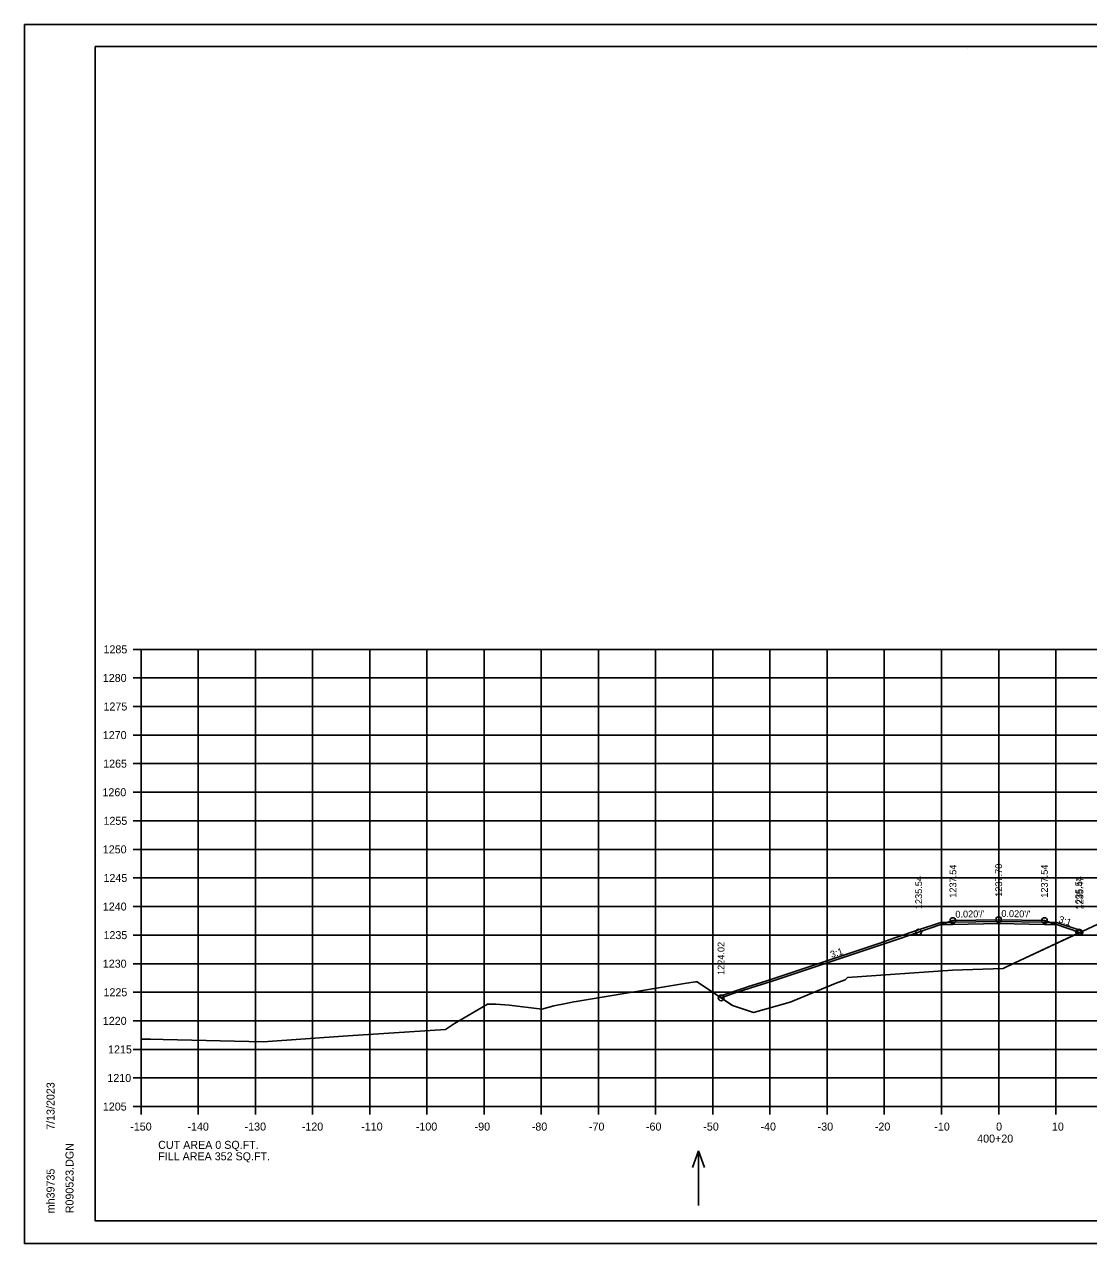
# Model space of a CAD drawing. Extents: x 1406028 to 1412453, y 321733 to 325986.
# Drawn here: x 1411612.8 to 1411799, y 322044.9 to 322258.3 of the extents above; entities that cross this region are included whole.
import ezdxf

# ---------------------------------------------------------------- set-up
doc = ezdxf.new("R2010")
doc.units = 0
for name, color, linetype in [('R_Alt Surface', 7, 'Continuous'), ('R_Axis', 7, 'Continuous'), ('R_Axis Annot', 7, 'Continuous'), ('R_Border', 7, 'Continuous'), ('R_Contours', 7, 'Continuous'), ('R_Exist Surface', 7, 'Continuous'), ('R_Fin Surface', 7, 'Continuous'), ('R_Fin Surface Annot', 7, 'Continuous'), ('R_Grid', 7, 'Continuous'), ('R_No Plot', 7, 'Continuous'), ('R_Water Annot', 7, 'Continuous')]:
    doc.layers.add(name, color=color, linetype=linetype)

msp = doc.modelspace()

# ---------------------------------------------------------------- linework, layer by layer
at = {"layer": 'R_Alt Surface'}
msp.add_lwpolyline([(1411773.11, 322100.74), (1411775.24, 322100.78), (1411783.24, 322100.94), (1411791.24, 322100.78), (1411793.38, 322100.74)], dxfattribs=at)
at = {"layer": 'R_Axis'}
for p, q in [((1411631.84, 322148.91), (1411633.24, 322148.91)), ((1411633.24, 322068.91), (1411633.24, 322148.91)), ((1411631.84, 322143.91), (1411633.24, 322143.91)), ((1411631.84, 322138.91), (1411633.24, 322138.91)), ((1411631.84, 322133.91), (1411633.24, 322133.91)), ((1411631.84, 322128.91), (1411633.24, 322128.91)), ((1411631.84, 322123.91), (1411633.24, 322123.91)), ((1411631.84, 322118.91), (1411633.24, 322118.91)), ((1411631.84, 322113.91), (1411633.24, 322113.91)), ((1411631.84, 322108.91), (1411633.24, 322108.91)), ((1411631.84, 322103.91), (1411633.24, 322103.91)), ((1411631.84, 322098.91), (1411633.24, 322098.91)), ((1411631.84, 322093.91), (1411633.24, 322093.91)), ((1411631.84, 322088.91), (1411633.24, 322088.91)), ((1411631.84, 322083.91), (1411633.24, 322083.91)), ((1411631.84, 322078.91), (1411633.24, 322078.91)), ((1411631.84, 322073.91), (1411633.24, 322073.91)), ((1411631.84, 322068.91), (1411633.24, 322068.91)), ((1411633.24, 322068.91), (1411933.24, 322068.91)), ((1411633.24, 322067.51), (1411633.24, 322068.91)), ((1411643.24, 322067.51), (1411643.24, 322068.91)), ((1411653.24, 322067.51), (1411653.24, 322068.91)), ((1411663.24, 322067.51), (1411663.24, 322068.91)), ((1411673.24, 322067.51), (1411673.24, 322068.91)), ((1411683.24, 322067.51), (1411683.24, 322068.91)), ((1411693.24, 322067.51), (1411693.24, 322068.91)), ((1411703.24, 322067.51), (1411703.24, 322068.91)), ((1411713.24, 322067.51), (1411713.24, 322068.91)), ((1411723.24, 322067.51), (1411723.24, 322068.91)), ((1411733.24, 322067.51), (1411733.24, 322068.91)), ((1411743.24, 322067.51), (1411743.24, 322068.91)), ((1411753.24, 322067.51), (1411753.24, 322068.91)), ((1411763.24, 322067.51), (1411763.24, 322068.91)), ((1411773.24, 322067.51), (1411773.24, 322068.91)), ((1411783.24, 322067.51), (1411783.24, 322068.91)), ((1411793.24, 322067.51), (1411793.24, 322068.91))]:
    msp.add_line(p, q, dxfattribs=at)
at = {"layer": 'R_Border'}
for p, q in [((1411625.24, 322254.37), (1411941.42, 322254.37)), ((1411625.24, 322048.91), (1411625.24, 322254.37)), ((1411777.76, 322254.11), (1411777.76, 322254.11)), ((1411777.76, 322254.11), (1411777.76, 322254.11)), ((1411625.24, 322048.91), (1411625.24, 322048.91)), ((1411941.42, 322048.91), (1411625.24, 322048.91))]:
    msp.add_line(p, q, dxfattribs=at)
at = {"layer": 'R_Contours'}
msp.add_lwpolyline([(1411734.31, 322088.18), (1411736.66, 322086.59), (1411740.33, 322085.39), (1411746.77, 322087.17), (1411754.63, 322090.45), (1411756.41, 322091.08), (1411756.82, 322091.49), (1411775.17, 322092.79), (1411784.02, 322093.09), (1411786.04, 322094.07), (1411797.92, 322099.6), (1411797.24, 322099.83), (1411793.38, 322101.12), (1411791.24, 322101.16), (1411783.24, 322101.32), (1411775.24, 322101.16), (1411773.11, 322101.12), (1411769.24, 322099.83), (1411768.84, 322099.69), (1411765.42, 322098.53), (1411762.11, 322097.38), (1411742.71, 322090.9), (1411739.3, 322089.84), (1411739.04, 322089.76)], close=True, dxfattribs=at)
at = {"layer": 'R_Exist Surface'}
msp.add_lwpolyline([(1411633.24, 322080.71), (1411634.9, 322080.71), (1411637.08, 322080.66), (1411654.6, 322080.23), (1411669.38, 322081.29), (1411686.46, 322082.42), (1411688.09, 322083.43), (1411693.81, 322086.81), (1411695.29, 322086.8), (1411697.69, 322086.65), (1411703.34, 322085.97), (1411705.42, 322086.53), (1411707.55, 322086.97), (1411708.93, 322087.22), (1411709.37, 322087.27), (1411728.66, 322090.53), (1411730.23, 322090.76), (1411730.5, 322090.76), (1411736.66, 322086.59), (1411740.33, 322085.39), (1411746.77, 322087.17), (1411754.63, 322090.45), (1411756.41, 322091.08), (1411756.82, 322091.49), (1411775.17, 322092.79), (1411784.02, 322093.09), (1411786.04, 322094.07), (1411800.57, 322100.83)], dxfattribs=at)
at = {"layer": 'R_Fin Surface'}
msp.add_lwpolyline([(1411734.68, 322087.93), (1411736.81, 322088.7), (1411739.88, 322089.67), (1411743.44, 322090.78), (1411762.52, 322097.15), (1411765.65, 322098.23), (1411769.24, 322099.45), (1411773.11, 322100.74), (1411775.24, 322101.45), (1411783.24, 322101.61), (1411791.24, 322101.45), (1411793.38, 322100.74), (1411797.24, 322099.45), (1411797.45, 322099.38)], dxfattribs=at)
at = {"layer": 'R_Grid'}
for p, q in [((1411633.24, 322148.91), (1411933.24, 322148.91)), ((1411633.24, 322068.91), (1411633.24, 322148.91)), ((1411643.24, 322068.91), (1411643.24, 322148.91)), ((1411653.24, 322068.91), (1411653.24, 322148.91)), ((1411663.24, 322068.91), (1411663.24, 322148.91)), ((1411673.24, 322068.91), (1411673.24, 322148.91)), ((1411683.24, 322068.91), (1411683.24, 322148.91)), ((1411693.24, 322068.91), (1411693.24, 322148.91)), ((1411703.24, 322068.91), (1411703.24, 322148.91)), ((1411713.24, 322068.91), (1411713.24, 322148.91)), ((1411723.24, 322068.91), (1411723.24, 322148.91)), ((1411733.24, 322068.91), (1411733.24, 322148.91)), ((1411743.24, 322068.91), (1411743.24, 322148.91)), ((1411753.24, 322068.91), (1411753.24, 322148.91)), ((1411763.24, 322068.91), (1411763.24, 322148.91)), ((1411773.24, 322068.91), (1411773.24, 322148.91)), ((1411783.24, 322068.91), (1411783.24, 322148.91)), ((1411793.24, 322068.91), (1411793.24, 322148.91)), ((1411633.24, 322143.91), (1411933.24, 322143.91)), ((1411633.24, 322138.91), (1411933.24, 322138.91)), ((1411633.24, 322133.91), (1411933.24, 322133.91)), ((1411633.24, 322128.91), (1411933.24, 322128.91)), ((1411633.24, 322123.91), (1411933.24, 322123.91)), ((1411633.24, 322118.91), (1411933.24, 322118.91)), ((1411633.24, 322113.91), (1411933.24, 322113.91)), ((1411633.24, 322108.91), (1411933.24, 322108.91)), ((1411633.24, 322103.91), (1411933.24, 322103.91)), ((1411633.24, 322098.91), (1411933.24, 322098.91)), ((1411633.24, 322093.91), (1411933.24, 322093.91)), ((1411633.24, 322088.91), (1411933.24, 322088.91)), ((1411633.24, 322083.91), (1411933.24, 322083.91)), ((1411633.24, 322078.91), (1411933.24, 322078.91)), ((1411633.24, 322073.91), (1411933.24, 322073.91)), ((1411633.24, 322068.91), (1411933.24, 322068.91))]:
    msp.add_line(p, q, dxfattribs=at)
at = {"layer": 'R_No Plot'}
for p, q in [((1411612.84, 322258.27), (1411946.18, 322258.27)), ((1411612.84, 322044.93), (1411946.18, 322044.93))]:
    msp.add_line(p, q, dxfattribs=at)
for points in [[(1411612.84, 322258.27), (1411946.18, 322258.27), (1411946.18, 322044.93), (1411612.84, 322044.93)], [(1411859.16, 322254.37), (1411878.78, 322254.37), (1411878.78, 322244.49), (1411894.9, 322244.49), (1411918.1, 322244.49), (1411918.1, 322220.16), (1411941.42, 322220.16), (1411941.42, 322048.91), (1411625.24, 322048.91), (1411625.24, 322254.37)]]:
    msp.add_lwpolyline(points, close=True, dxfattribs=at)
for centre in [(1411775.24, 322101.45), (1411775.24, 322101.45), (1411783.24, 322101.61), (1411791.24, 322101.45), (1411791.24, 322101.45), (1411769.24, 322099.45), (1411797.24, 322099.45), (1411797.45, 322099.38), (1411797.45, 322099.38), (1411734.68, 322087.93)]:
    msp.add_circle(centre, 0.5, dxfattribs=at)
at = {"layer": 'R_Water Annot'}
for p, q in [((1411730.74, 322061.19), (1411729.67, 322058.26)), ((1411730.74, 322051.61), (1411730.74, 322061.19)), ((1411730.74, 322061.19), (1411731.8, 322058.26))]:
    msp.add_line(p, q, dxfattribs=at)

# ---------------------------------------------------------------- texts
at = {"layer": 'R_Axis Annot'}
for s, p in [('1285', (1411626.67, 322148.21)), ('1280', (1411626.55, 322143.21)), ('1275', (1411626.67, 322138.21)), ('1270', (1411626.55, 322133.21)), ('1265', (1411626.61, 322128.21)), ('1260', (1411626.49, 322123.21)), ('1255', (1411626.67, 322118.21)), ('1250', (1411626.55, 322113.21)), ('1245', (1411626.67, 322108.21)), ('1240', (1411626.55, 322103.21)), ('1235', (1411626.67, 322098.21)), ('1230', (1411626.55, 322093.21)), ('1225', (1411626.67, 322088.21)), ('1220', (1411626.55, 322083.21)), ('1215', (1411627.47, 322078.21)), ('1210', (1411627.35, 322073.21)), ('1205', (1411626.56, 322068.21)), ('-150', (1411631.35, 322064.71)), ('-140', (1411641.35, 322064.71)), ('-130', (1411651.35, 322064.71)), ('-120', (1411661.35, 322064.71)), ('-110', (1411671.75, 322064.71)), ('-100', (1411681.3, 322064.71)), ('-90', (1411691.58, 322064.71)), ('-80', (1411701.58, 322064.71)), ('-70', (1411711.58, 322064.71)), ('-60', (1411721.55, 322064.71)), ('-50', (1411731.58, 322064.71)), ('-40', (1411741.58, 322064.71)), ('-30', (1411751.58, 322064.71)), ('-20', (1411761.58, 322064.71)), ('-10', (1411771.98, 322064.71)), ('0', (1411782.79, 322064.71)), ('10', (1411792.55, 322064.71)), ('400+20', (1411779.48, 322062.61)), ('CUT AREA 0 SQ.FT.', (1411636.24, 322061.51)), ('FILL AREA 352 SQ.FT.', (1411636.24, 322059.51))]:
    msp.add_text(s, height=1.4, dxfattribs=at).set_placement(p)
at = {"layer": 'R_Border'}
for s, p in [('7/13/2023', (1411618.11, 322064.84)), ('R090523.DGN', (1411621.43, 322050.24)), ('mh39735', (1411618.11, 322050.24))]:
    msp.add_text(s, height=1.4, rotation=90, dxfattribs=at).set_placement(p)
at = {"layer": 'R_Fin Surface Annot'}
for s, rotation, p in [('1237.54', 90, (1411775.84, 322105.45)), ('1237.70', 90, (1411783.84, 322105.61)), ('1237.54', 90, (1411791.84, 322105.45)), ('1235.54', 90, (1411769.84, 322103.45)), ('1235.54', 90, (1411797.84, 322103.45)), ('1235.47', 90, (1411798.05, 322103.38)), ("0.020'/'", 1.1458, (1411775.67, 322101.96)), ("0.020'/'", 358.8542, (1411783.69, 322102.1)), ('3:1', 341.5651, (1411793.61, 322101.19)), ('1224.02', 90, (1411735.28, 322091.93)), ('3:1', 18.4349, (1411754.02, 322094.9))]:
    msp.add_text(s, height=1.2, rotation=rotation, dxfattribs=at).set_placement(p)

doc.saveas('drawing.dxf')
